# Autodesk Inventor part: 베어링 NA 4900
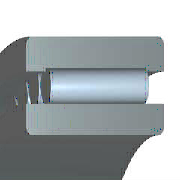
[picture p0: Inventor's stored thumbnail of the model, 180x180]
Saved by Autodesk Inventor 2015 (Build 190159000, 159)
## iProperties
Created: 2009-02
Part Number: 베어링 NA 4900
Material: Steel, Mild
Description: 니들 롤러 베어링 - 경계 치수 및 공차
Document SubType Name: Modeling
Standard: KS B 2029
Designer: SeoGD™
Standards Organization: KS
Language: ko-KR
Size Designation: NA 4900 - 10 x 22 x 13
Categories: <MemberInstance><Categories><Category DisplayName="샤프트 부품" InternalName="7f7aeb1f-a693-4053-b835-cee3144e0d98" Mnemonic="SHFT"><Category DisplayName="베어링" Inter
Density: 1 g/cm^3
Appearance: Metal-Steel
IsCustomPart: 0
Author: SeoGD™
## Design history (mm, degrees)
sketch "스케치"
  geometry: L1 (1.857, 9)-(11.143, 9); L2 (11.143, 9)-(11.143, 7); L3 (13, 7)-(0, 7); L4 (1.857, 7)-(1.857, 9); L5 (1.857, 8)-(11.143, 8); L6 (6.5, 8)-(6.5, 7); L7 (0, 5)-(13, 5); L8 (0, 11)-(13, 11); L9 (13, 5)-(13, 7); L10 (13, 8.8)-(13, 11); L11 (1.857, 8.8)-(0, 8.8); L12 (11.143, 8.8)-(13, 8.8); L13 (-6, 0)-(36, 0) reference; L14 (0, -1.9)-(0, 14.9) reference
  constraints: 24 end point, 8 point on line, 3 midpoint, 3 parallel, 3 perpendicular, 2 symmetric about line, 1 horizontal, 1 other
  dimensions: "d6" = 10 diameter of L7 L13 (= WD); "d7" = 14 diameter of L3 L13 (= KID1); "d8" = 22 diameter of L8 L13 (= BD); "d9" = 16 diameter of L6.start L13 (= 0.5 x WD + 0.5 x BD); "d10" = 17.6 diameter of L12 L13 (= 0.9 x BD + 0.9 x WD - 0.8 x KID1); "d11" = 18 diameter of L1 L13 (= BD + WD - KID1); "d12" = 1.85714 distance between parallel lines of L14 L4 (= 0.142857 x KB); "d13" = 13 distance between parallel lines of L14 L9 (= KB); "d14" = 11.14286 distance between parallel lines of L14 L2 (= 0.857143 x KB)
revolve "본체" stored, may be unused: angle "d17" = 90 deg
revolve "롤러" stored, may be unused: angle "d18" = 90 deg
pattern_circular "IDS_ARRAYROLLER[SIMPL:T]" dims angle "d2" = 360 deg
body "Solid1"
fillet "모깎기1" dims "d0" = 0.3 (= KRS)
other parameters: "WD" = 10 [user parameter; used in 6 equation terms], "BD" = 22 [user parameter; used in 6 equation terms], "KB" = 13 [user parameter; used in 3 equation terms], "KID1" = 14 [user parameter; used in 4 equation terms], "KRS" = 0.3 [user parameter; used in 1 equation term], "d3" = 0, "d4" = 0, "d5" = 0, "d15" = 0, "d16" = 0, "BC0" = 9150000 [user parameter], "WR" = 5 (= 0.5 x WD) [user parameter], "BBA" = 0 [user parameter], "BC" = 8150000 [user parameter], "BR" = 11 (= 0.5 x BD) [user parameter]
